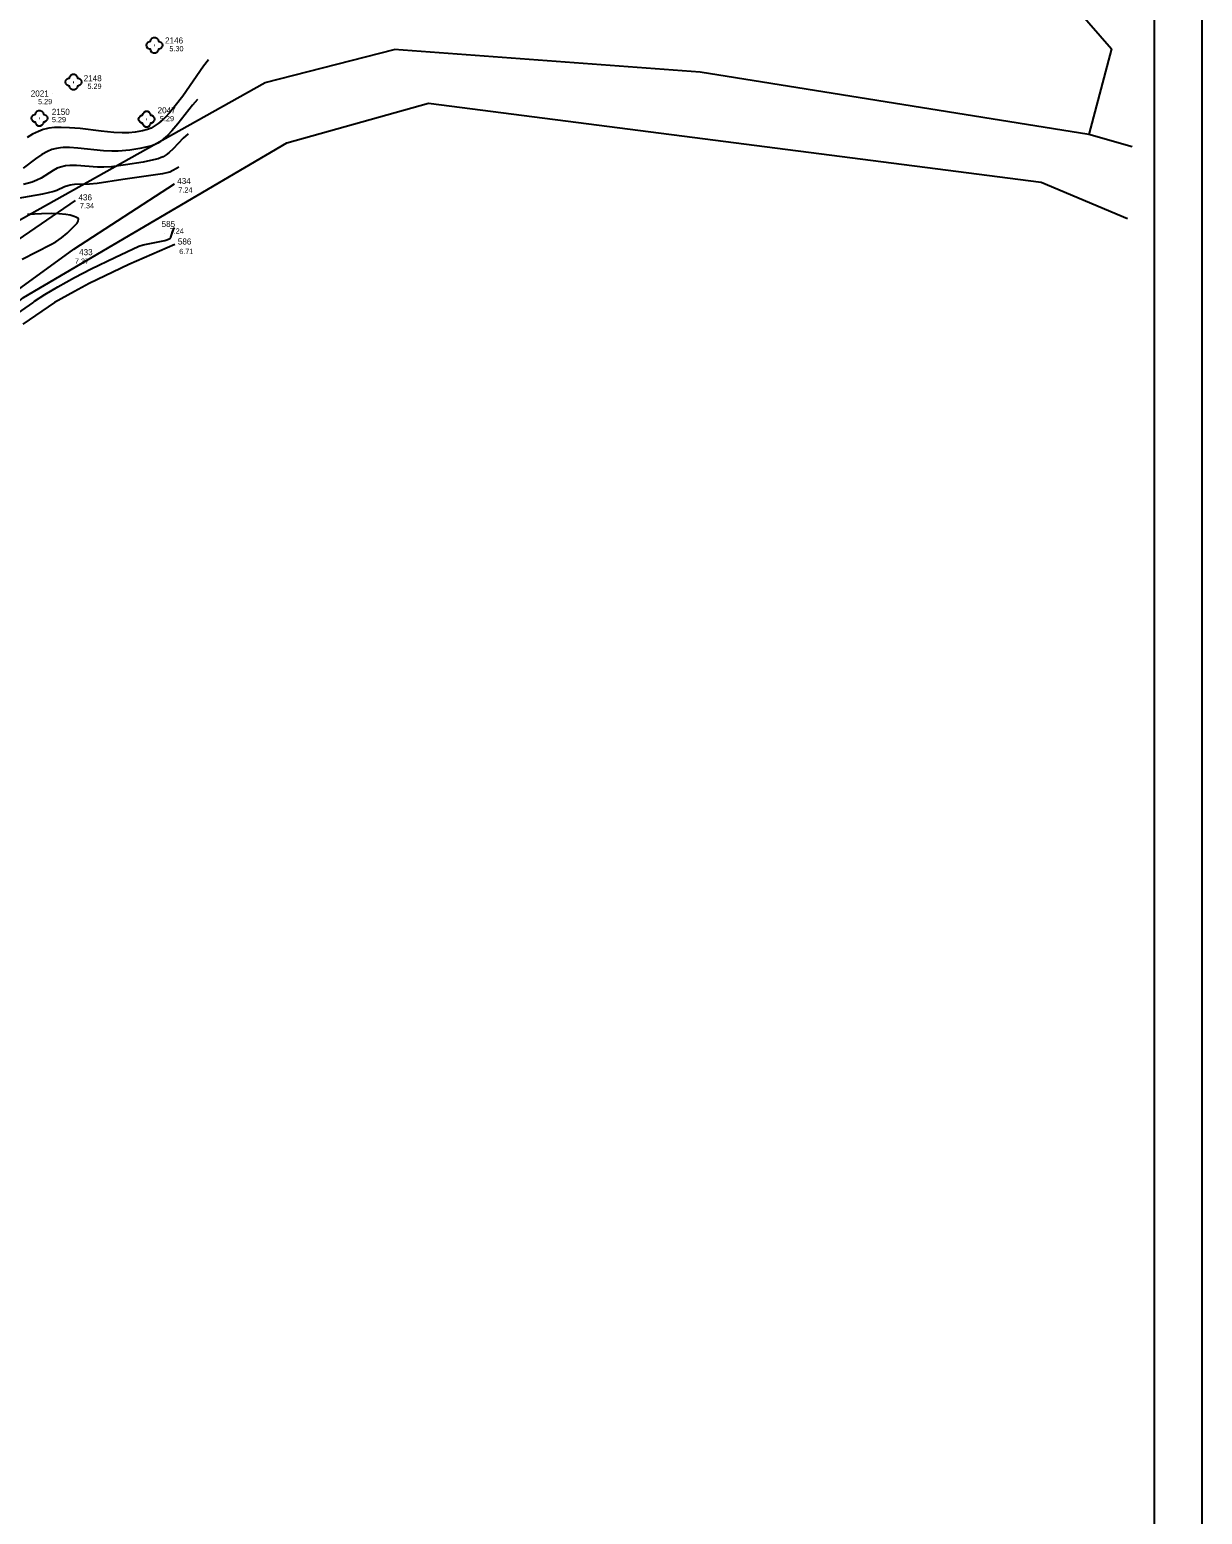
# Model space of a CAD drawing. Extents: x -792549 to -792339, y -1111914 to -1111617.
# Drawn here: x -792412.2 to -792338.6, y -1111801.9 to -1111708.7 of the extents above; entities that cross this region are included whole.
import ezdxf

# ---------------------------------------------------------------- set-up
doc = ezdxf.new("R2010")
doc.units = 0
for name, color, linetype in [('Vrstva 1', 7, 'Continuous'), ('Vrstva 10', 7, 'Continuous'), ('Vrstva 24', 7, 'Continuous'), ('Vrstva 32', 7, 'Continuous'), ('Vrstva 33', 7, 'Continuous'), ('Vrstva 41', 7, 'Continuous'), ('Vrstva 44', 7, 'Continuous'), ('Vrstva 47', 7, 'Continuous'), ('Vrstva 48', 7, 'Continuous'), ('Vrstva 49', 7, 'Continuous'), ('Vrstva 50', 7, 'Continuous'), ('Vrstva 60', 7, 'Continuous')]:
    doc.layers.add(name, color=color, linetype=linetype)

# ---------------------------------------------------------------- blocks, each defined once
blk = doc.blocks.new('SC6231')
at = {"layer": 'Vrstva 1'}
blk.add_line((0, 0), (0, 0), dxfattribs=at)
blk = doc.blocks.new('3$1301')
at = {"layer": 'Vrstva 1'}
for points in [[(20, 0), (19, -4.3), (16.2, -7.8), (12.2, -9.7), (10, -10), (9, -14.3), (6.2, -17.8), (2.2, -19.7), (-2.3, -19.7), (-6.3, -17.8), (-9.1, -14.3), (-10.1, -10), (-12.3, -9.7), (-16.3, -7.8), (-19.1, -4.3), (-20.1, 0), (-19.1, 4.3), (-16.3, 7.8), (-12.3, 9.7), (-10.1, 10), (-9.1, 14.3), (-6.3, 17.8), (-2.3, 19.7), (2.2, 19.7), (6.2, 17.8), (9, 14.3), (10, 10), (12.2, 9.7), (16.2, 7.8), (19, 4.3), (20, 0)], [(-0.5, 0), (0, 0), (0.5, 0)]]:
    blk.add_lwpolyline(points, dxfattribs=at)

msp = doc.modelspace()

# ---------------------------------------------------------------- linework, layer by layer
at = {"layer": 'Vrstva 10'}
msp.add_lwpolyline([(-792403.07, -1111722.15), (-792405.94, -1111723.41), (-792408.43, -1111724.6), (-792409.36, -1111725.09), (-792410.61, -1111725.8), (-792412.6, -1111727.14)], dxfattribs=at)
at = {"layer": 'Vrstva 24'}
msp.add_lwpolyline([(-792545.564, -1111620.164), (-792545.564, -1111911.164), (-792341.564, -1111911.164), (-792341.564, -1111620.164)], close=True, dxfattribs=at)
at = {"layer": 'Vrstva 32'}
for points in [[(-792401.637, -1111713.04), (-792401.948, -1111713.397), (-792402.872, -1111714.578), (-792403.241, -1111715.011), (-792403.524, -1111715.308), (-792403.764, -1111715.525), (-792403.971, -1111715.685), (-792404.134, -1111715.785), (-792404.247, -1111715.842), (-792404.512, -1111715.944), (-792404.779, -1111716.02), (-792405.262, -1111716.124), (-792405.883, -1111716.221), (-792406.615, -1111716.291), (-792407.02, -1111716.295), (-792407.548, -1111716.263), (-792409.14, -1111716.092), (-792409.668, -1111716.062), (-792410.079, -1111716.068), (-792410.242, -1111716.078), (-792410.492, -1111716.113), (-792410.772, -1111716.19), (-792411.055, -1111716.31), (-792411.404, -1111716.507), (-792411.803, -1111716.779), (-792412.581, -1111717.353)], [(-792402.806, -1111717.304), (-792402.948, -1111717.367), (-792403.18, -1111717.505), (-792403.37, -1111717.598), (-792403.471, -1111717.628), (-792403.845, -1111717.705), (-792406.318, -1111718.066), (-792407.927, -1111718.313), (-792408.416, -1111718.367), (-792409.359, -1111718.387), (-792409.505, -1111718.399), (-792409.63, -1111718.42), (-792409.785, -1111718.459), (-792409.98, -1111718.536), (-792410.458, -1111718.752), (-792410.652, -1111718.819), (-792411.359, -1111718.984), (-792414.372, -1111719.516)], [(-792411.982, -1111725.811), (-792411.866, -1111725.708), (-792411.221, -1111725.292), (-792410.395, -1111724.796), (-792409.362, -1111724.224), (-792408.307, -1111723.678), (-792406.831, -1111722.959), (-792405.316, -1111722.25), (-792405.047, -1111722.172), (-792403.686, -1111721.894), (-792403.553, -1111721.857), (-792403.413, -1111721.802), (-792403.38, -1111721.782), (-792403.321, -1111721.697), (-792403.12, -1111721.137), (-792403.076, -1111721.073)], [(-792414.424, -1111727.571), (-792413.151, -1111726.632), (-792411.982, -1111725.811)]]:
    msp.add_lwpolyline(points, dxfattribs=at)
at = {"layer": 'Vrstva 33'}
for points in [[(-792400.957, -1111710.559), (-792401.256, -1111710.945), (-792402.565, -1111712.837), (-792403.03, -1111713.452), (-792403.4, -1111713.888), (-792403.666, -1111714.168), (-792403.925, -1111714.406), (-792404.109, -1111714.56), (-792404.418, -1111714.766), (-792404.552, -1111714.84), (-792404.787, -1111714.938), (-792405.083, -1111715.017), (-792405.548, -1111715.1), (-792405.956, -1111715.136), (-792406.366, -1111715.143), (-792406.899, -1111715.118), (-792407.693, -1111715.036), (-792409.013, -1111714.874), (-792409.667, -1111714.815), (-792410.202, -1111714.796), (-792410.615, -1111714.809), (-792410.978, -1111714.847), (-792411.147, -1111714.882), (-792411.334, -1111714.934), (-792411.623, -1111715.047), (-792411.986, -1111715.23), (-792412.322, -1111715.437)], [(-792402.23, -1111715.203), (-792402.529, -1111715.48), (-792403.159, -1111716.139), (-792403.417, -1111716.377), (-792403.599, -1111716.522), (-792403.786, -1111716.636), (-792403.912, -1111716.691), (-792404.108, -1111716.761), (-792404.409, -1111716.843), (-792405.045, -1111716.973), (-792406.164, -1111717.152), (-792407.047, -1111717.263), (-792407.508, -1111717.296), (-792407.911, -1111717.294), (-792409.24, -1111717.199), (-792409.643, -1111717.196), (-792409.914, -1111717.217), (-792410.245, -1111717.287), (-792410.441, -1111717.364), (-792410.708, -1111717.505), (-792411.455, -1111717.976), (-792411.719, -1111718.117), (-792412.016, -1111718.239), (-792412.555, -1111718.39)], [(-792412.646, -1111723.068), (-792410.841, -1111722.156), (-792410.531, -1111721.978), (-792410.18, -1111721.728), (-792409.823, -1111721.43), (-792409.479, -1111721.104), (-792409.202, -1111720.804), (-792409.122, -1111720.676), (-792409.103, -1111720.565), (-792409.16, -1111720.504), (-792409.272, -1111720.435), (-792409.371, -1111720.394), (-792409.623, -1111720.316), (-792409.898, -1111720.265), (-792410.341, -1111720.224), (-792410.831, -1111720.209), (-792411.428, -1111720.218), (-792412.303, -1111720.272)]]:
    msp.add_lwpolyline(points, dxfattribs=at)
at = {"layer": 'Vrstva 41'}
for points in [[(-792402.71, -1111664.98), (-792361.64, -1111689.93), (-792344.27, -1111709.86), (-792345.69, -1111715.24), (-792370.08, -1111711.34), (-792389.29, -1111709.91)], [(-792444.71, -1111766.33), (-792434.44, -1111743.01), (-792441.66, -1111747.03), (-792441.97, -1111752.1), (-792445.31, -1111753.45), (-792459.79, -1111725.74), (-792456.34, -1111722.07), (-792447.22, -1111740.16), (-792434.96, -1111737.57), (-792416.43, -1111722.62), (-792397.39, -1111711.98), (-792389.29, -1111709.91)], [(-792434.44, -1111743.01), (-792412.56, -1111725.48), (-792396.04, -1111715.77), (-792387.14, -1111713.27)], [(-792387.14, -1111713.27), (-792348.68, -1111718.24), (-792343.266, -1111720.509)], [(-792342.969, -1111716.01), (-792345.69, -1111715.24)]]:
    msp.add_lwpolyline(points, dxfattribs=at)
at = {"layer": 'Vrstva 47'}
for points in [[(-792409.31, -1111719.38), (-792418.34, -1111725.56), (-792424.82, -1111730.4), (-792430.22, -1111734.34), (-792434.41, -1111737.13), (-792442.38, -1111740.78), (-792445.75, -1111740.01), (-792449.54, -1111736.26), (-792452.26, -1111731.65), (-792454.7, -1111727.15), (-792457.13, -1111721.97), (-792458.5, -1111716.6), (-792458.46, -1111713.25), (-792457.09, -1111710.06)], [(-792462.35, -1111715.02), (-792460.88, -1111719.83), (-792457.78, -1111726.1), (-792454.62, -1111732.8), (-792451.65, -1111738.37), (-792446.17, -1111745.03), (-792441.97, -1111744.32), (-792431.56, -1111738.6), (-792425.09, -1111733.75), (-792415.96, -1111727.2), (-792409.4, -1111722.44), (-792403.09, -1111718.34)]]:
    msp.add_lwpolyline(points, dxfattribs=at)
at = {"layer": 'Vrstva 60'}
msp.add_lwpolyline([(-792548.564, -1111617.164), (-792548.564, -1111914.164), (-792338.564, -1111914.164), (-792338.564, -1111617.164), (-792548.564, -1111617.164)], dxfattribs=at)

# ---------------------------------------------------------------- block references
at = {"layer": 'Vrstva 44', "xscale": 0.025, "yscale": 0.025000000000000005}
for p in [(-792404.34, -1111709.64), (-792409.42, -1111711.95), (-792411.56, -1111714.22), (-792404.83, -1111714.28)]:
    msp.add_blockref('3$1301', p, dxfattribs=at)
at = {"layer": 'Vrstva 48', "xscale": 0.1, "yscale": 0.10000000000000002}
for p in [(-792404.34, -1111709.64), (-792409.42, -1111711.95), (-792410.77, -1111712.69), (-792411.56, -1111714.22), (-792404.83, -1111714.28), (-792403.09, -1111718.34), (-792409.31, -1111719.38), (-792403.7, -1111721.44), (-792409.4, -1111722.44), (-792403.07, -1111722.15)]:
    msp.add_blockref('SC6231', p, dxfattribs=at)

# ---------------------------------------------------------------- texts
at = {"layer": 'Vrstva 49'}
for s, p in [('2146', (-792403.673, -1111709.53)), ('2148', (-792408.783, -1111711.9)), ('2021', (-792412.105, -1111712.86)), ('2047', (-792404.143, -1111713.91)), ('2150', (-792410.783, -1111714.01)), ('434', (-792402.91, -1111718.35)), ('436', (-792409.111, -1111719.38)), ('585', (-792403.891, -1111721.05)), ('586', (-792402.871, -1111722.15)), ('433', (-792409.071, -1111722.82))]:
    msp.add_text(s, height=0.38, dxfattribs=at).set_placement(p)
at = {"layer": 'Vrstva 50'}
for s, p in [('5.30', (-792403.403, -1111710.02)), ('5.29', (-792408.547, -1111712.38)), ('5.29', (-792411.647, -1111713.34)), ('5.29', (-792410.777, -1111714.47)), ('5.29', (-792403.997, -1111714.41)), ('7.24', (-792402.839, -1111718.89)), ('7.34', (-792409.019, -1111719.88)), ('7.24', (-792403.389, -1111721.47)), ('6.71', (-792402.789, -1111722.75)), ('7.37', (-792409.333, -1111723.36))]:
    msp.add_text(s, height=0.33, dxfattribs=at).set_placement(p)

doc.saveas('drawing.dxf')
